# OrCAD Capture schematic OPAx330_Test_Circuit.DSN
size A; title: OPAx330 50-µV VOS, 0.25-µV/°C, 35-µA CMOS Operational; rev: 1.3; note: Datasheet: SBOS432G EVM: N/A
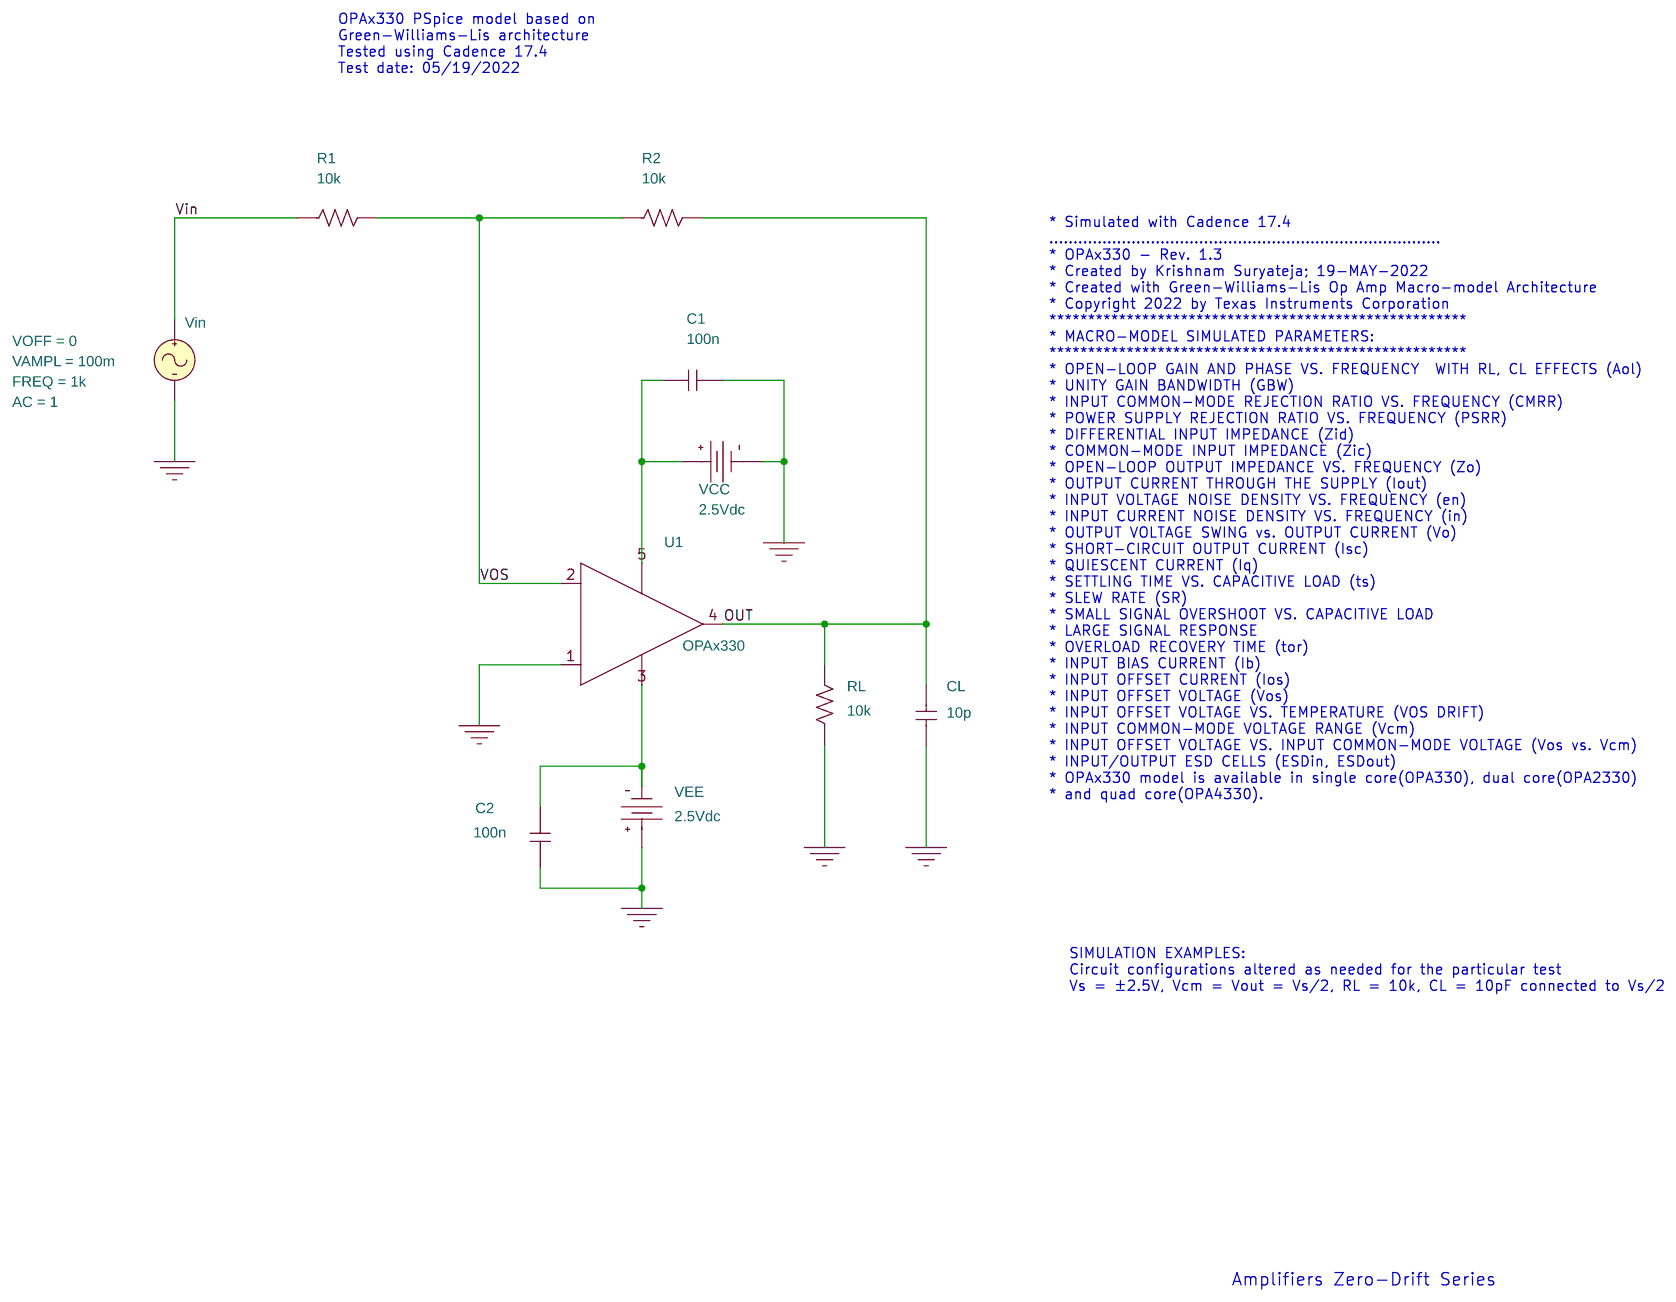
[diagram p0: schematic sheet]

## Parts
C1  100n  [cap196]
C2  100n  [cap196]
CL  10p  [cap196]
R1  10k  [AXRC05]
R2  10k  [AXRC05]
RL  10k  [AXRC05]
U1  OPAx330
VCC  VDC
VEE  VDC
Vin  VSIN

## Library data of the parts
C1 C2 CL = C
R1 R2 RL = R
U1 = OPAx330
VCC VEE = VDC: DC: 2.5Vdc
Vin = VSIN: AC: 1; FREQ: 1k; VAMPL: 100m; VOFF: 0

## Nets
Vin: R1.1 Vin.1(+)
0: C1.2 C2.1 CL.2 RL.1 U1.1(+) VCC.1(-) VEE.0(+) Vin.2(-)
OUT: CL.1 R2.2 RL.2 U1.4(OUT)
VOS: R1.2 R2.1 U1.2(-)
N27303: C1.1 U1.5(V+) VCC.0(+)
N27354: C2.2 U1.3(V-) VEE.1(-)

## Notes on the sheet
- OPAx330 PSpice model based on
  Green-Williams-Lis architecture
  Tested using Cadence 17.4
  Test date: 05/19/2022
- * Simulated with Cadence 17.4
  .................................................................................
  * OPAx330 - Rev. 1.3
  * Created by Krishnam Suryateja; 19-MAY-2022
  * Created with Green-Williams-Lis Op Amp Macro-model Architecture
  * Copyright 2022 by Texas Instruments Corporation
  ******************************************************
  * MACRO-MODEL SIMULATED PARAMETERS:
  ******************************************************
  * OPEN-LOOP GAIN AND PHASE VS. FREQUENCY  WITH RL, CL EFFECTS (Aol)
  * UNITY GAIN BANDWIDTH (GBW)
  * INPUT COMMON-MODE REJECTION RATIO VS. FREQUENCY (CMRR)
  * POWER SUPPLY REJECTION RATIO VS. FREQUENCY (PSRR)
  * DIFFERENTIAL INPUT IMPEDANCE (Zid)
  * COMMON-MODE INPUT IMPEDANCE (Zic)
  * OPEN-LOOP OUTPUT IMPEDANCE VS. FREQUENCY (Zo)
  * OUTPUT CURRENT THROUGH THE SUPPLY (Iout)
  * INPUT VOLTAGE NOISE DENSITY VS. FREQUENCY (en)
  * INPUT CURRENT NOISE DENSITY VS. FREQUENCY (in)
  * OUTPUT VOLTAGE SWING vs. OUTPUT CURRENT (Vo)
  * SHORT-CIRCUIT OUTPUT CURRENT (Isc)
  * QUIESCENT CURRENT (Iq)
  * SETTLING TIME VS. CAPACITIVE LOAD (ts)
  * SLEW RATE (SR)
  * SMALL SIGNAL OVERSHOOT VS. CAPACITIVE LOAD
  * LARGE SIGNAL RESPONSE
  * OVERLOAD RECOVERY TIME (tor)
  * INPUT BIAS CURRENT (Ib)
  * INPUT OFFSET CURRENT (Ios)
  * INPUT OFFSET VOLTAGE (Vos)
  * INPUT OFFSET VOLTAGE VS. TEMPERATURE (VOS DRIFT)
  * INPUT COMMON-MODE VOLTAGE RANGE (Vcm)
  * INPUT OFFSET VOLTAGE VS. INPUT COMMON-MODE VOLTAGE (Vos vs. Vcm)
  * INPUT/OUTPUT ESD CELLS (ESDin, ESDout)
  * OPAx330 model is available in single core(OPA330), dual core(OPA2330)
  * and quad core(OPA4330).
- SIMULATION EXAMPLES:
  Circuit configurations altered as needed for the particular test
  Vs = ±2.5V, Vcm = Vout = Vs/2, RL = 10k, CL = 10pF connected to Vs/2
- Amplifiers Zero-Drift Series
